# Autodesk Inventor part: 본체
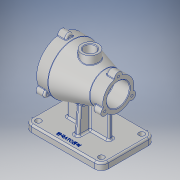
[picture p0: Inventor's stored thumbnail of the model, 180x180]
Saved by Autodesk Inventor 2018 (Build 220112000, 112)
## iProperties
Created: 2020-03
Part Number: 본체
Material: 알루미늄 6061
Document SubType Name: Modeling
Designer: USER
Density: 2.7 g/cm^3
Appearance: 알루미늄 - 평지
Mass: 999.489 g
Surface Area: 863.413 cm^2
Volume: 370.181 cm^3
Author: USER
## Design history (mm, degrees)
sketch "스케치1"
  geometry: L1 (0, 0)-(100, 0); L2 (100, 0)-(100, 27.5); L3 (100, 27.5)-(77, 27.5); L4 (77, 27.5)-(20, 44); L5 (20, 44)-(0, 44); L6 (0, 44)-(0, 0); L7 (0, 0)-(107.225, 0)
  constraints: 14 end point, 3 perpendicular, 2 horizontal, 1 parallel
  dimensions: "d0" = 20 distance from line of L4.end L6; "d1" = 55 diameter of L3 L7; "d2" = 100 distance between parallel lines of L2 L6; "d3" = 77 distance from line of L3.end L6; "d4" = 88 diameter of L5 L7
revolve "회전1" sketch "스케치1" stored, may be unused: angle "d5" = 90 deg
sketch "스케치2"
  geometry: L1 (0, 0)-(23, 0); L2 (23, 0)-(23, 36); L3 (23, 36)-(0, 36); L4 (0, 36)-(0, 0); L5 (23, 0)-(70, 0); L6 (70, 0)-(70, 26); L7 (70, 26)-(23, 26); L8 (23, 26)-(23, 0); L9 (70, 0)-(100, 0); L10 (100, 0)-(100, 20); L11 (100, 20)-(70, 20); L12 (70, 20)-(70, 0); L13 (100, -27.5)-(100, 27.5) reference; L14 (0, 0)-(130.943, 0)
  constraints: 26 end point, 6 parallel, 4 horizontal, 3 perpendicular, 1 midpoint
  dimensions: "d6" = 40 diameter of L11 L14; "d7" = 52 diameter of L7 L14; "d8" = 72 diameter of L3 L14; "d9" = 23 distance between parallel lines of L2 L4; "d10" = 47 distance between parallel lines of L6 L2
revolve "회전2" sketch "스케치2" stored, may be unused: angle "d11" = 90 deg
node "작업 평면1"
sketch "스케치3"
  geometry: C1 r 15 at (-50, 0); 1 further point
  constraints: 1 centre point, 1 horizontal alignment
  dimensions: "d13" = 30 diameter of C1; "d14" = 50 distance of point (0, 0) C1.centre
extrude "돌출1" join sketch "스케치3" stored distance "d15" = 10; taper "d16" = 0 deg
sketch "스케치4"
  geometry: C1 r 15 at (0, 0) reference; C2 r 10 at (0, 0); 1 further point
  constraints: 1 centre point, 1 coincident
  dimensions: "d17" = 20 diameter of C2
extrude "돌출2" cut sketch "스케치4" distance "d18" = 25.75; taper "d19" = 0 deg
node "작업 평면2"
sketch "스케치6"
  geometry: L1 (0, 44)-(0, -44) reference; L2 (-100, 27.5)-(-100, -27.5) reference; L3 (17.5, -47.5)-(-117.5, -47.5); L4 (-117.5, -47.5)-(-117.5, 47.5); L5 (-117.5, 47.5)-(17.5, 47.5); L6 (17.5, 47.5)-(17.5, -47.5); L7 (0, 0)-(-100, 0); L8 (-50, 0)-(-50, -25.303)
  constraints: 12 end point, 2 midpoint, 2 parallel, 1 horizontal, 1 perpendicular, 1 vertical, 1 other
  dimensions: "d21" = 135 distance between parallel lines of L4 L6; "d22" = 95 distance between parallel lines of L5 L3; "d23" = 47.5 distance from line of L7.start L3
extrude "돌출3" join sketch "스케치6" distance "d24" = 12; taper "d25" = 0 deg
fillet "모깎기1" dims "d26" = 12
sketch "스케치7"
  geometry: L1 (13, 4)-(87, 4); L2 (87, 4)-(87, -4); L3 (87, -4)-(13, -4); L4 (13, -4)-(13, 4); L5 (117.5, 35.5)-(117.5, -35.5) reference; L6 (-17.5, -35.5)-(-17.5, 35.5) reference; L7 (-17.5, 0)-(117.5, 0); L8 (50, 0)-(50, 35.5); 1 further point
  constraints: 12 end point, 3 midpoint, 2 parallel, 1 horizontal, 1 perpendicular, 1 vertical, 1 other
  dimensions: "d27" = 74 distance between parallel lines of L2 L4; "d28" = 8 distance between parallel lines of L3 L1; "d29" = 4 distance from line of point (0, 0) L1
extrude "돌출4" join sketch "스케치7" stored distance "d30" = 12; taper "d31" = 0 deg
node "작업 평면3"
sketch "스케치8"
  geometry: L1 (39.5, 12)-(39.5, 43.182) reference; L2 (31.5, 12)-(39.5, 12) reference; L3 (31.5, 12)-(31.5, 43.182) reference; L4 (31.5, 12)-(39.5, 12) reference; L5 (10.5, 12)-(31.5, 12); L6 (71, 12)-(0, 12) reference; L7 (10.5, 12)-(14.999, 63.425); L8 (14.999, 63.425)-(31.5, 53.896); L9 (31.5, 53.896)-(31.5, 12); L10 (-12, 12)-(0, 12) reference; L11 (35.5, 43)-(35.5, 12); C1 r 36 at (35.5, 87) reference; C2 r 36 at (35.5, 87) reference; C3 r 44 at (35.5, 87) reference; A1 r 44 centre (35.5, 87) between (31.5, 43.182) and (39.5, 43.182) reference; A2 r 44 centre (35.5, 87) between (31.5, 43.182) and (39.5, 43.182) reference; 1 further point
  constraints: 10 end point, 2 point on circle, 1 midpoint, 1 point on line, 1 vertical
  dimensions: "d35" = 95 deg angle of L10 L7; "d91" = 25 distance from line of L11 L5.start
extrude "돌출5" join sketch "스케치8" stored distance "d36" = 8; taper "d37" = 0 deg
sketch "스케치9"
  geometry: L1 (0, 0)-(0, 72.213); C1 r 7 at (0, 44); A1 r 44 centre (0, 0) between (-4, -43.818) and (4, -43.818) reference; A2 r 44 centre (0, 0) between (4, -43.818) and (-4, -43.818) reference; 1 further point
  constraints: 2 end point, 1 centre point, 1 point on circle, 1 point on line, 1 vertical
  dimensions: "d38" = 14 diameter of C1
extrude "돌출6" join sketch "스케치9" distance "d39" = 15; taper "d40" = 0 deg
sketch "스케치10"
  geometry: A1 r 44 centre (0, -44) between (6.978, -0.557) and (-6.978, -0.557) reference; 2 further points
  constraints: 1 point on circle
hole "구멍1" sketch "스케치10" at (0, 0) diameter "d41" = 4.134; stored, may be unused: countersink angle "d45" = 90 deg, drill point angle "d47" = 118 deg; dims "d42" = 9, "d43" = 4, "d44" = 2, "d46" = 11
sketch "스케치11"
  geometry: L1 (0, 0)-(0, 40.117); C1 r 20 at (0, 0) reference; C2 r 7 at (0, 27.5); A1 r 27.5 centre (0, 0) between (4, -27.208) and (-4, -27.208) reference; A2 r 27.5 centre (0, 0) between (4, -27.208) and (-4, -27.208) reference; 1 further point
  constraints: 2 end point, 1 centre point, 1 point on circle, 1 point on line, 1 vertical
  dimensions: "d51" = 14 diameter of C2
extrude "돌출7" join sketch "스케치11" distance "d52" = 15; taper "d53" = 0 deg
sketch "스케치12"
  geometry: A1 r 7 centre (0, 0) between (6.943, -0.891) and (-6.943, -0.891) reference; 1 further point
hole "구멍2" sketch "스케치12" at (0, 0) diameter "d54" = 4.134; stored, may be unused: countersink angle "d58" = 90 deg, drill point angle "d60" = 118 deg; dims "d55" = 9, "d56" = 4, "d57" = 2, "d59" = 11
sketch "스케치13"
  geometry: L1 (-5.5, 47.5)-(105.5, 47.5) reference; L2 (117.5, 35.5)-(117.5, -35.5) reference; L3 (105.5, -47.5)-(-5.5, -47.5) reference; L4 (-17.5, -35.5)-(-17.5, 35.5) reference; C1 r 5 at (-5.5, 35.5); C2 r 5 at (105.5, 35.5); C3 r 5 at (105.5, -35.5); C4 r 5 at (-5.5, -35.5); A1 r 12 centre (-5.5, 35.5) between (-5.5, 47.5) and (-17.5, 35.5) reference; A2 r 12 centre (105.5, -35.5) between (105.5, -47.5) and (117.5, -35.5) reference; A3 r 12 centre (-5.5, 35.5) between (-5.5, 47.5) and (-17.5, 35.5) reference; A4 r 12 centre (105.5, 35.5) between (117.5, 35.5) and (105.5, 47.5) reference; A5 r 12 centre (105.5, -35.5) between (105.5, -47.5) and (117.5, -35.5) reference; A6 r 12 centre (-5.5, -35.5) between (-17.5, -35.5) and (-5.5, -47.5) reference; 1 further point
  constraints: 4 centre point, 4 coincident
  dimensions: "d64" = 10 diameter of C1; "d65" = 10 diameter of C2; "d66" = 10 diameter of C3; "d67" = 10 diameter of C4
extrude "돌출8" cut sketch "스케치13" distance "d68" = 15; taper "d69" = 0 deg
fillet "모깎기2" dims "d70" = 3
fillet "모깎기4" dims "d72" = 3
fillet "모깎기5" dims "d73" = 3
fillet "모깎기6" dims "d74" = 3
fillet "모깎기7" dims "d75" = 1
fillet "모깎기8" dims "d76" = 3
chamfer "모따기1" distance "d77" = 1; stored, may be unused: second distance "d78" = 2, angle "d79" = 45 deg
chamfer "모따기2" distance "d80" = 1; stored, may be unused: second distance "d81" = 2, angle "d82" = 45 deg
fillet "모깎기9" dims "d83" = 3
node "작업 평면4"
sketch "스케치15"
  geometry: L1 (-5.5, -47.5)-(105.5, -47.5) reference; L2 (117.5, -35.5)-(117.5, 35.5) reference; 2 further points
  constraints: 1 other
  dimensions: "d85" = 10 distance from line of L1 point (50, -37.5); "d86" = 67.5 distance from line of L2 point (50, -37.5)
feature "엠보싱1" sketch "스케치15" dims "d6" = 40, "d7" = 52, "d8" = 72, "d9" = 23, "d10" = 47, "d87" = 0.5, "d88" = 0
fillet "모깎기10" dims "d89" = 1
fillet "모깎기11" dims "d92" = 3
node "솔리드1"
mirror "미러1"
pattern_circular "원형 패턴1" dims angle "d49" = 360 deg
pattern_circular "원형 패턴2" dims angle "d62" = 360 deg
node "투영된 루프1"
node "투영된 루프2"
node "투영된 루프3"
node "투영된 루프4"
other parameters: "d12" = 45, "d20" = -87, "d32" = -67.5
